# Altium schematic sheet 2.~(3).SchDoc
size 420 x 297 mm
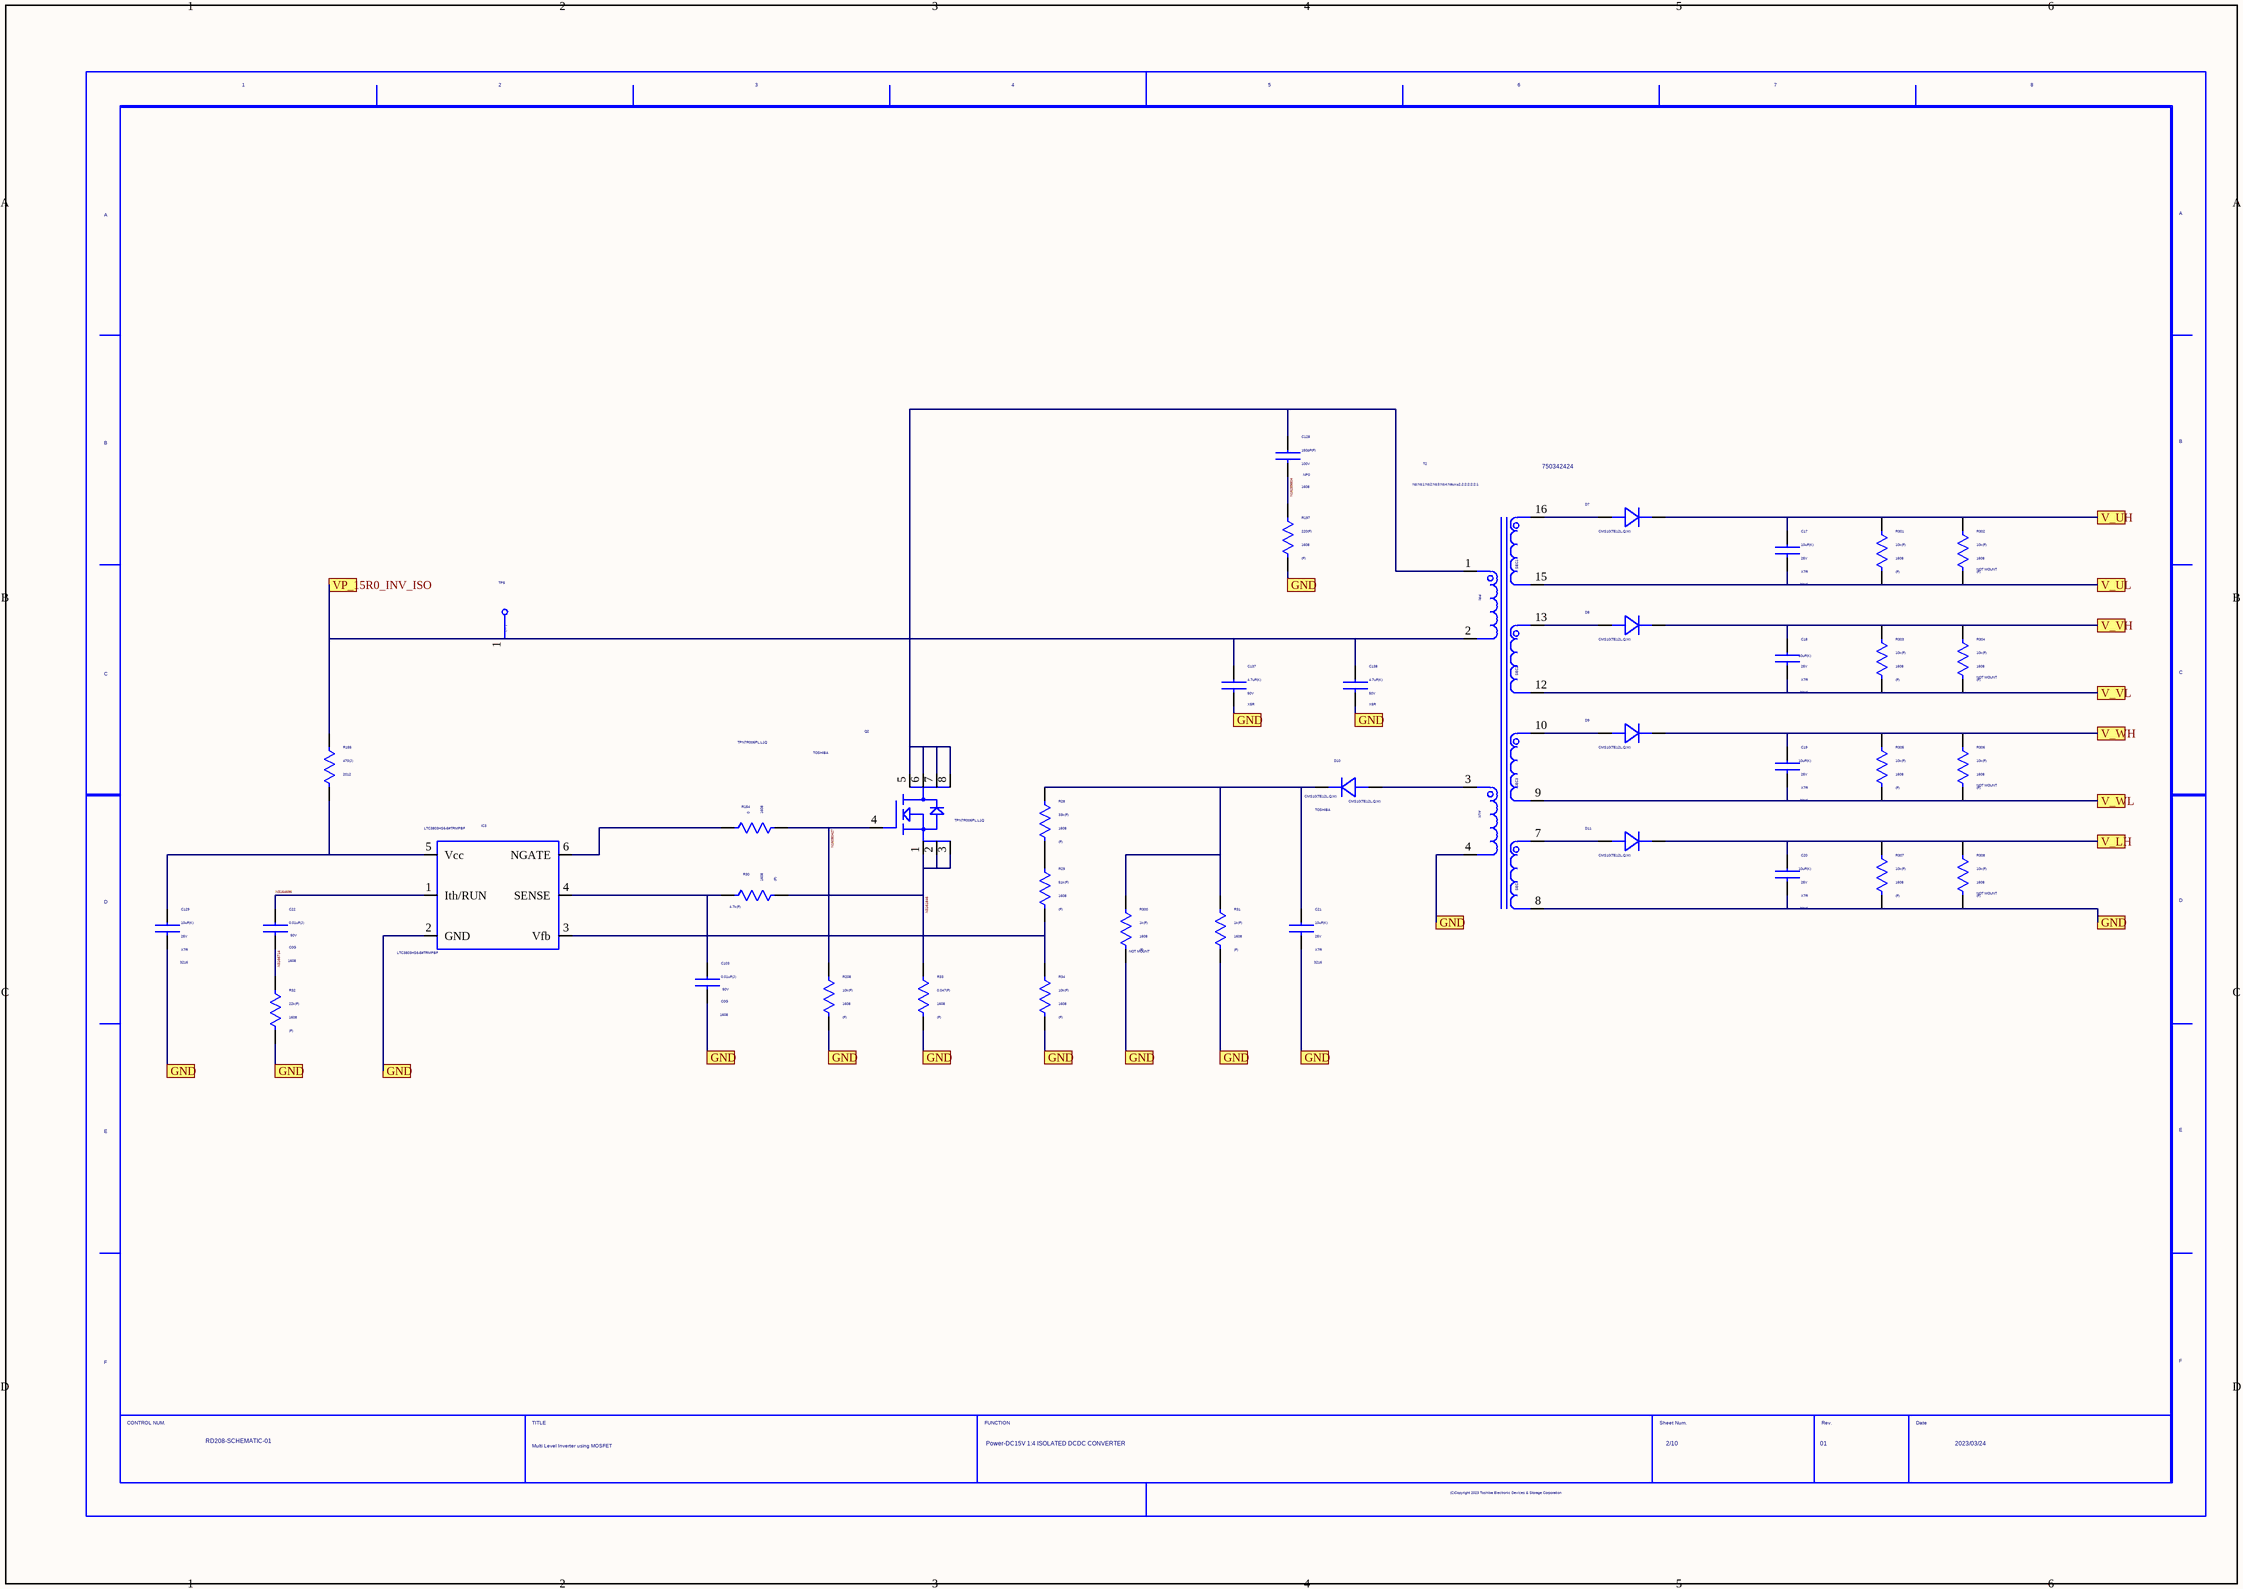
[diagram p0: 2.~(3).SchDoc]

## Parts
C17  VAL2: 25V  SIZECODESMD: 3216  VALUE4: X7R  VAL1: 10uF(K)  (hidden comment: GRM31CR71E106MA12K)
C18  VAL2: 25V  SIZECODESMD: 3216  VALUE4: X7R  VAL1: 10uF(K)  (hidden comment: GRM31CR71E106MA12K)
C19  VAL2: 25V  SIZECODESMD: 3216  VALUE4: X7R  VAL1: 10uF(K)  (hidden comment: GRM31CR71E106MA12K)
C20  VAL2: 25V  SIZECODESMD: 3216  VALUE4: X7R  VAL1: 10uF(K)  (hidden comment: GRM31CR71E106MA12K)
C21  VAL2: 25V  SIZECODESMD: 3216  VALUE4: X7R  VAL1: 10uF(K)  (hidden comment: GRM31CR71E106MA12K)
C22  VAL2: 50V  SIZECODESMD: 1608  VALUE4: C0G  VAL1: 0.01uF(J)  (hidden comment: GRM1885C1H103JA01J)
C103  VAL2: 50V  SIZECODESMD: 1608  VALUE4: C0G  VAL1: 0.01uF(J)  (hidden comment: GRM1885C1H103JA01J)
C128  VAL2: 100V  SIZECODESMD: 1608  VALUE4: NP0  VAL1: 150pF(F)  (hidden comment: 06031A151FAT2A)
C129  VAL2: 25V  SIZECODESMD: 3216  VALUE4: X7R  VAL1: 10uF(K)  (hidden comment: GRM31CR71E106MA12K)
C137  VAL2: 50V  SIZECODESMD: 2012  VALUE4: X5R  VAL1: 4.7uF(K)  (hidden comment: GRM21BR61H475KE51L)
C138  VAL2: 50V  SIZECODESMD: 2012  VALUE4: X5R  VAL1: 4.7uF(K)  (hidden comment: GRM21BR61H475KE51L)
D7  VAL1: CMS10(TE12L,Q,M)  (hidden comment: CMS10_TE12L,Q,M_)
D8  VAL1: CMS10(TE12L,Q,M)  (hidden comment: CMS10_TE12L,Q,M_)
D9  VAL1: CMS10(TE12L,Q,M)  (hidden comment: CMS10_TE12L,Q,M_)
D10  VAL1: CMS10(TE12L,Q,M)  USERCOMPTEXT3: TOSHIBA  (hidden comment: CMS10_TE12L,Q,M_)
D11  VAL1: CMS10(TE12L,Q,M)  (hidden comment: CMS10_TE12L,Q,M_)
IC3  VAL1: LTC3803HS6-5#TRMPBF  (hidden comment: LTC3803HS6_5#TRMPBF)
Q2  USERCOMPTEXT3: TOSHIBA  (hidden comment: TPN7R006PL,L1Q)
R28  SIZECODESMD: 1608  VALUE4: (F)  VAL1: 33k(F)  (hidden comment: ERJ3EKF3302V)
R29  SIZECODESMD: 1608  VALUE4: (F)  VAL1: 51k(F)  (hidden comment: ERJ3EKF5102V)
R30  SIZECODESMD: 1608  VALUE4: (F)  VAL1: 4.7k(F)  (hidden comment: ERJ3EKF4701V)
R31  SIZECODESMD: 1608  VALUE4: (F)  VAL1: 1k(F)  (hidden comment: ERJ3EKF1001V)
R32  SIZECODESMD: 1608  VALUE4: (F)  VAL1: 22k(F)  (hidden comment: ERJ3EKF2202V)
R33  SIZECODESMD: 1608  VALUE4: (F)  VAL1: 0.047(F)  (hidden comment: WSLP0603R0470FEA)
R34  SIZECODESMD: 1608  VALUE4: (F)  VAL1: 10k(F)  (hidden comment: ERJ3EKF1002V)
R154  SIZECODESMD: 1608  VAL1: 0  (hidden comment: ERJ3GEY0R00V)
R155  SIZECODESMD: 2012  VAL1: 470(J)  (hidden comment: ERJP06J471V)
R197  SIZECODESMD: 1608  VALUE4: (F)  VAL1: 220(F)  (hidden comment: ERJ3EKF2200V)
R208  SIZECODESMD: 1608  VALUE4: (F)  VAL1: 10k(F)  (hidden comment: ERJ3EKF1002V)
R300  SIZECODESMD: 1608  VALUE4: (F)  VAL1: 1k(F)  NOTMOUNT: NOT MOUNT  (hidden comment: ERJ3EKF1001V)
R301  SIZECODESMD: 1608  VALUE4: (F)  VAL1: 10k(F)  (hidden comment: ERJ3EKF1002V)
R302  SIZECODESMD: 1608  VALUE4: (F)  VAL1: 10k(F)  NOTMOUNT: NOT MOUNT  (hidden comment: ERJ3EKF1002V)
R303  SIZECODESMD: 1608  VALUE4: (F)  VAL1: 10k(F)  (hidden comment: ERJ3EKF1002V)
R304  SIZECODESMD: 1608  VALUE4: (F)  VAL1: 10k(F)  NOTMOUNT: NOT MOUNT  (hidden comment: ERJ3EKF1002V)
R305  SIZECODESMD: 1608  VALUE4: (F)  VAL1: 10k(F)  (hidden comment: ERJ3EKF1002V)
R306  SIZECODESMD: 1608  VALUE4: (F)  VAL1: 10k(F)  NOTMOUNT: NOT MOUNT  (hidden comment: ERJ3EKF1002V)
R307  SIZECODESMD: 1608  VALUE4: (F)  VAL1: 10k(F)  (hidden comment: ERJ3EKF1002V)
R308  SIZECODESMD: 1608  VALUE4: (F)  VAL1: 10k(F)  NOTMOUNT: NOT MOUNT  (hidden comment: ERJ3EKF1002V)
T2  VAL2: Np:Ns1:Ns2:Ns3:Ns4:Naux=2.2:2:2:2:2:1  (hidden comment: 750342424)
TP5  TP  (value not drawn)
U?  DATE: 2023/03/24  TITLE: Multi Level Inverter using MOSFET  REVISION: 01  SHEETNUMBER: 2/10  DRAWINGNUMBER: RD208-SCHEMATIC-01  FUNCTION: Power-DC15V 1:4 ISOLATED DCDC CONVERTER  (hidden comment: WAKU_DEF100)

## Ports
GND, V_LH, V_UH, V_UL, V_VH, V_VL, V_WH, V_WL, VP_15R0_INV_ISO

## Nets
GND: C20.2 C21.2 C103.2 C129.2 C137.2 C138.2 IC3.2(GND) R31.2 R32.2 R33.2 R34.2 R197.2 R208.2 R300.2 R307.2 R308.2 T2.4 T2.8 ; port GND
L3803_FB: C103.1 IC3.3(Vfb) IC3.4(SENSE) R29.2 R30.1 R34.1  [also labelled L3803_SENSE]
L3803_NGATE: IC3.6(NGATE) R154.1
L3803_VCC: C129.1 IC3.5(Vcc) R155.2
N3161846: Q2.1(S1) Q2.2(S2) Q2.3(S3) R30.2 R33.1
N3164696: C22.1 IC3.1(Ith/RUN)
N3166714: C22.2 R32.1
N16080427: Q2.4(G) R154.2 R208.1
N16289804: C128.2 R197.1
TRANS2_AUX: D10.A(ANODE) T2.3
TRANS2_AUX_B: C21.1 D10.K(CATHODE) R28.1 R31.1 R300.1
TRANS2_PRI: C128.1 Q2.5(D1) Q2.6(D2) Q2.7(D3) Q2.8(D4) T2.1
TRANS2_SEC1: D7.A(ANODE) T2.16
TRANS2_SEC2: D8.A(ANODE) T2.13
TRANS2_SEC3: D9.A(ANODE) T2.10
TRANS2_SEC4: D11.A(ANODE) T2.7
V_LH: C20.1 D11.K(CATHODE) R307.1 R308.1 ; port V_LH
V_UH: C17.1 D7.K(CATHODE) R301.1 R302.1 ; port V_UH
V_UL: C17.2 R301.2 R302.2 T2.15 ; port V_UL
V_VH: C18.1 D8.K(CATHODE) R303.1 R304.1 ; port V_VH
V_VL: C18.2 R303.2 R304.2 T2.12 ; port V_VL
V_WH: C19.1 D9.K(CATHODE) R305.1 R306.1 ; port V_WH
V_WL: C19.2 R305.2 R306.2 T2.9 ; port V_WL
VP_15R0_INV_ISO: C137.1 C138.1 R155.1 T2.2 TP5.1 ; port VP_15R0_INV_ISO
NetR28_2: R28.2 R29.1

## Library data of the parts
C17 = GRM31CR71E106MA12K: MANUFACTURER: MURATA; ITEM: CAP Ceramic; TIME: 08:44:46; UPDATEUSER: t5459927; SAVECOUNT: 1; OriginalSymbolOrigin: (0,0); INSTANCENAME: INS3167698
C18 = GRM31CR71E106MA12K: MANUFACTURER: MURATA; ITEM: CAP Ceramic; TIME: 08:44:46; UPDATEUSER: t5459927; SAVECOUNT: 1; OriginalSymbolOrigin: (0,0); INSTANCENAME: INS3170101
C19 = GRM31CR71E106MA12K: MANUFACTURER: MURATA; ITEM: CAP Ceramic; TIME: 08:44:46; UPDATEUSER: t5459927; SAVECOUNT: 1; OriginalSymbolOrigin: (0,0); INSTANCENAME: INS3170299
C20 = GRM31CR71E106MA12K: MANUFACTURER: MURATA; ITEM: CAP Ceramic; TIME: 08:44:46; UPDATEUSER: t5459927; SAVECOUNT: 1; OriginalSymbolOrigin: (0,0); INSTANCENAME: INS3170601
C21 = GRM31CR71E106MA12K: MANUFACTURER: MURATA; ITEM: CAP Ceramic; TIME: 08:44:46; UPDATEUSER: t5459927; SAVECOUNT: 1; OriginalSymbolOrigin: (0,0); INSTANCENAME: INS3166051
C22 = GRM1885C1H103JA01J: MANUFACTURER: MURATA; ITEM: CAP Ceramic; TIME: 08:44:46; UPDATEUSER: t5459927; SAVECOUNT: 1; OriginalSymbolOrigin: (0,0); INSTANCENAME: INS3166637
C103 = GRM1885C1H103JA01J: MANUFACTURER: MURATA; ITEM: CAP Ceramic; TIME: 08:44:46; UPDATEUSER: t5459927; SAVECOUNT: 1; OriginalSymbolOrigin: (0,0); INSTANCENAME: INS16080669
C128 = 06031A151FAT2A: MANUFACTURER: AVX; ITEM: CAP Ceramic; TIME: 08:44:46; UPDATEUSER: t5459927; SAVECOUNT: 1; OriginalSymbolOrigin: (0,0); INSTANCENAME: INS16121206
C129 = GRM31CR71E106MA12K: MANUFACTURER: MURATA; ITEM: CAP Ceramic; TIME: 08:44:46; UPDATEUSER: t5459927; SAVECOUNT: 1; OriginalSymbolOrigin: (0,0); INSTANCENAME: INS16615608
C137 = GRM21BR61H475KE51L: MANUFACTURER: MURATA; ITEM: CAP Ceramic; TIME: 08:44:46; UPDATEUSER: t5459927; SAVECOUNT: 1; OriginalSymbolOrigin: (0,0); INSTANCENAME: INS17252024
C138 = GRM21BR61H475KE51L: MANUFACTURER: MURATA; ITEM: CAP Ceramic; TIME: 08:44:46; UPDATEUSER: t5459927; SAVECOUNT: 1; OriginalSymbolOrigin: (0,0); INSTANCENAME: INS17252038
D7 = CMS10_TE12L,Q,M_: MANUFACTURER: TOSHIBA; COMP: CMS10; ITEM: DIODE; TIME: 08:44:46; UPDATEUSER: t5459927; SAVECOUNT: 1; OriginalSymbolOrigin: (0,0); INSTANCENAME: INS3167754
D8 = CMS10_TE12L,Q,M_: MANUFACTURER: TOSHIBA; COMP: CMS10; ITEM: DIODE; TIME: 08:44:46; UPDATEUSER: t5459927; SAVECOUNT: 1; OriginalSymbolOrigin: (0,0); INSTANCENAME: INS3170061
D9 = CMS10_TE12L,Q,M_: MANUFACTURER: TOSHIBA; COMP: CMS10; ITEM: DIODE; TIME: 08:44:46; UPDATEUSER: t5459927; SAVECOUNT: 1; OriginalSymbolOrigin: (0,0); INSTANCENAME: INS3170259
D10 = CMS10_TE12L,Q,M_: COMP: CMS10; ITEM: DIODE; TIME: 08:44:46; UPDATEUSER: t5459927; SAVECOUNT: 1; OriginalSymbolOrigin: (0,0); INSTANCENAME: INS3165224
D11 = CMS10_TE12L,Q,M_: MANUFACTURER: TOSHIBA; COMP: CMS10; ITEM: DIODE; TIME: 08:44:46; UPDATEUSER: t5459927; SAVECOUNT: 1; OriginalSymbolOrigin: (0,0); INSTANCENAME: INS3170561
IC3 = LTC3803HS6_5#TRMPBF: MANUFACTURER: Analog Devices; ITEM: IC DCDC; VAL2: DCDC CONTROLLER; COMP: LTC3803HS6-5_TRMPBF; TIME: 08:44:46; UPDATEUSER: PS4_common_PC; UPDATETIME: 15:55:48; SAVECOUNT: 3; SAVEAREA0: -42732,-39864,65274,9349; OriginalSymbolOrigin: (0,0)
Q2 = TPN7R006PL,L1Q: ITEM: FET; COMP: TPN7R006PL_L1Q; ORDER: 0; TIME: 08:44:46; UPDATEUSER: t5459927; SAVECOUNT: 1; OriginalSymbolOrigin: (0,0); INSTANCENAME: INS3164116
R28 = ERJ3EKF3302V: MANUFACTURER: Panasonic; ITEM: Register; VAL2: 100mW; TIME: 08:44:46; UPDATEUSER: t5459927; SAVECOUNT: 1; OriginalSymbolOrigin: (0,0); INSTANCENAME: INS15947925
R29 = ERJ3EKF5102V: MANUFACTURER: Panasonic; ITEM: Register; VAL2: 100mW; TIME: 08:44:46; UPDATEUSER: t5459927; SAVECOUNT: 1; OriginalSymbolOrigin: (0,0); INSTANCENAME: INS15947972
R30 = ERJ3EKF4701V: MANUFACTURER: Panasonic; ITEM: Register; VAL2: 100mW; TIME: 08:44:46; UPDATEUSER: t5459927; SAVECOUNT: 1; OriginalSymbolOrigin: (0,0); INSTANCENAME: INS15947636
R31 = ERJ3EKF1001V: MANUFACTURER: Panasonic; ITEM: Register; VAL2: 100mW; TIME: 08:44:46; UPDATEUSER: t5459927; SAVECOUNT: 1; OriginalSymbolOrigin: (0,0); INSTANCENAME: INS15954881
R32 = ERJ3EKF2202V: MANUFACTURER: Panasonic; ITEM: Register; VAL2: 100mW; TIME: 08:44:46; UPDATEUSER: t5459927; SAVECOUNT: 1; OriginalSymbolOrigin: (0,0); INSTANCENAME: INS16644073
R33 = WSLP0603R0470FEA: MANUFACTURER: Vishay; ITEM: Register; VAL2: 400mW; TIME: 08:44:47; UPDATEUSER: t5459927; SAVECOUNT: 1; OriginalSymbolOrigin: (0,0); INSTANCENAME: INS15955052
R34 = ERJ3EKF1002V: MANUFACTURER: Panasonic; ITEM: Register; VAL2: 100mW; TIME: 08:44:46; UPDATEUSER: t5459927; SAVECOUNT: 1; OriginalSymbolOrigin: (0,0); INSTANCENAME: INS15947827
R154 = ERJ3GEY0R00V: MANUFACTURER: Panasonic; ITEM: Register; VAL2: 1/10W; TIME: 08:44:45; UPDATEUSER: t5459927; SAVECOUNT: 1; OriginalSymbolOrigin: (0,0); INSTANCENAME: INS16643171
R155 = ERJP06J471V: MANUFACTURER: Panasonic; ITEM: Register; VAL2: 500mW; VALUE4: (J); TIME: 08:44:46; UPDATEUSER: t5459927; SAVECOUNT: 1; OriginalSymbolOrigin: (0,0); INSTANCENAME: INS16122030
R197 = ERJ3EKF2200V: MANUFACTURER: Panasonic; ITEM: Register; VAL2: 100mW; TIME: 08:44:46; UPDATEUSER: t5459927; SAVECOUNT: 1; OriginalSymbolOrigin: (0,0); INSTANCENAME: INS16121237
R208 = ERJ3EKF1002V: MANUFACTURER: Panasonic; ITEM: Register; VAL2: 100mW; TIME: 08:44:46; UPDATEUSER: t5459927; SAVECOUNT: 1; OriginalSymbolOrigin: (0,0); INSTANCENAME: INS16643191
R300 = ERJ3EKF1001V: MANUFACTURER: Panasonic; ITEM: Register; VAL2: 100mW; TIME: 08:44:46; UPDATEUSER: t5459927; SAVECOUNT: 1; OriginalSymbolOrigin: (0,0); INSTANCENAME: INS17177028
R301 = ERJ3EKF1002V: MANUFACTURER: Panasonic; ITEM: Register; VAL2: 100mW; TIME: 08:44:46; UPDATEUSER: t5459927; SAVECOUNT: 1; OriginalSymbolOrigin: (0,0); INSTANCENAME: INS17199274
R302 = ERJ3EKF1002V: MANUFACTURER: Panasonic; ITEM: Register; VAL2: 100mW; TIME: 08:44:46; UPDATEUSER: t5459927; SAVECOUNT: 1; OriginalSymbolOrigin: (0,0); INSTANCENAME: INS17199242
R303 = ERJ3EKF1002V: MANUFACTURER: Panasonic; ITEM: Register; VAL2: 100mW; TIME: 08:44:46; UPDATEUSER: t5459927; SAVECOUNT: 1; OriginalSymbolOrigin: (0,0); INSTANCENAME: INS17198846
R304 = ERJ3EKF1002V: MANUFACTURER: Panasonic; ITEM: Register; VAL2: 100mW; TIME: 08:44:46; UPDATEUSER: t5459927; SAVECOUNT: 1; OriginalSymbolOrigin: (0,0); INSTANCENAME: INS17199336
R305 = ERJ3EKF1002V: MANUFACTURER: Panasonic; ITEM: Register; VAL2: 100mW; TIME: 08:44:46; UPDATEUSER: t5459927; SAVECOUNT: 1; OriginalSymbolOrigin: (0,0); INSTANCENAME: INS17198902
R306 = ERJ3EKF1002V: MANUFACTURER: Panasonic; ITEM: Register; VAL2: 100mW; TIME: 08:44:46; UPDATEUSER: t5459927; SAVECOUNT: 1; OriginalSymbolOrigin: (0,0); INSTANCENAME: INS17199378
R307 = ERJ3EKF1002V: MANUFACTURER: Panasonic; ITEM: Register; VAL2: 100mW; TIME: 08:44:46; UPDATEUSER: t5459927; SAVECOUNT: 1; OriginalSymbolOrigin: (0,0); INSTANCENAME: INS17198958
R308 = ERJ3EKF1002V: MANUFACTURER: Panasonic; ITEM: Register; VAL2: 100mW; TIME: 08:44:46; UPDATEUSER: t5459927; SAVECOUNT: 1; OriginalSymbolOrigin: (0,0); INSTANCENAME: INS17199357
T2 = 750342424: MANUFACTURER: WURTH; ITEM: Transformer; TIME: 08:44:46; UPDATEUSER: t5459927; SAVECOUNT: 1; OriginalSymbolOrigin: (0,2540); INSTANCENAME: INS3163135
TP5 = TP: TIME: 16:12:21; UPDATEUSER: fukuda-y; UPDATETIME: 16:18:11; SAVECOUNT: 2; SAVEAREA0: -242,-92,12810,7836; OriginalSymbolOrigin: (0,7620); VAL3: TH Hole dia. 1.0; COMP: TP-TH1.0-L1.6
U? = WAKU_DEF100: PLOTTIME: HH:MM; SAVEAREA0: 185750,-43960,448537,75779; TIME: 14:30:25; UPDATEUSER: PS4_common_PC; UPDATETIME: 08:23:32; SAVECOUNT: 8; OriginalSymbolOrigin: (10160,284480)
